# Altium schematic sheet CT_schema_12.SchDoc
size 386 x 278 mm
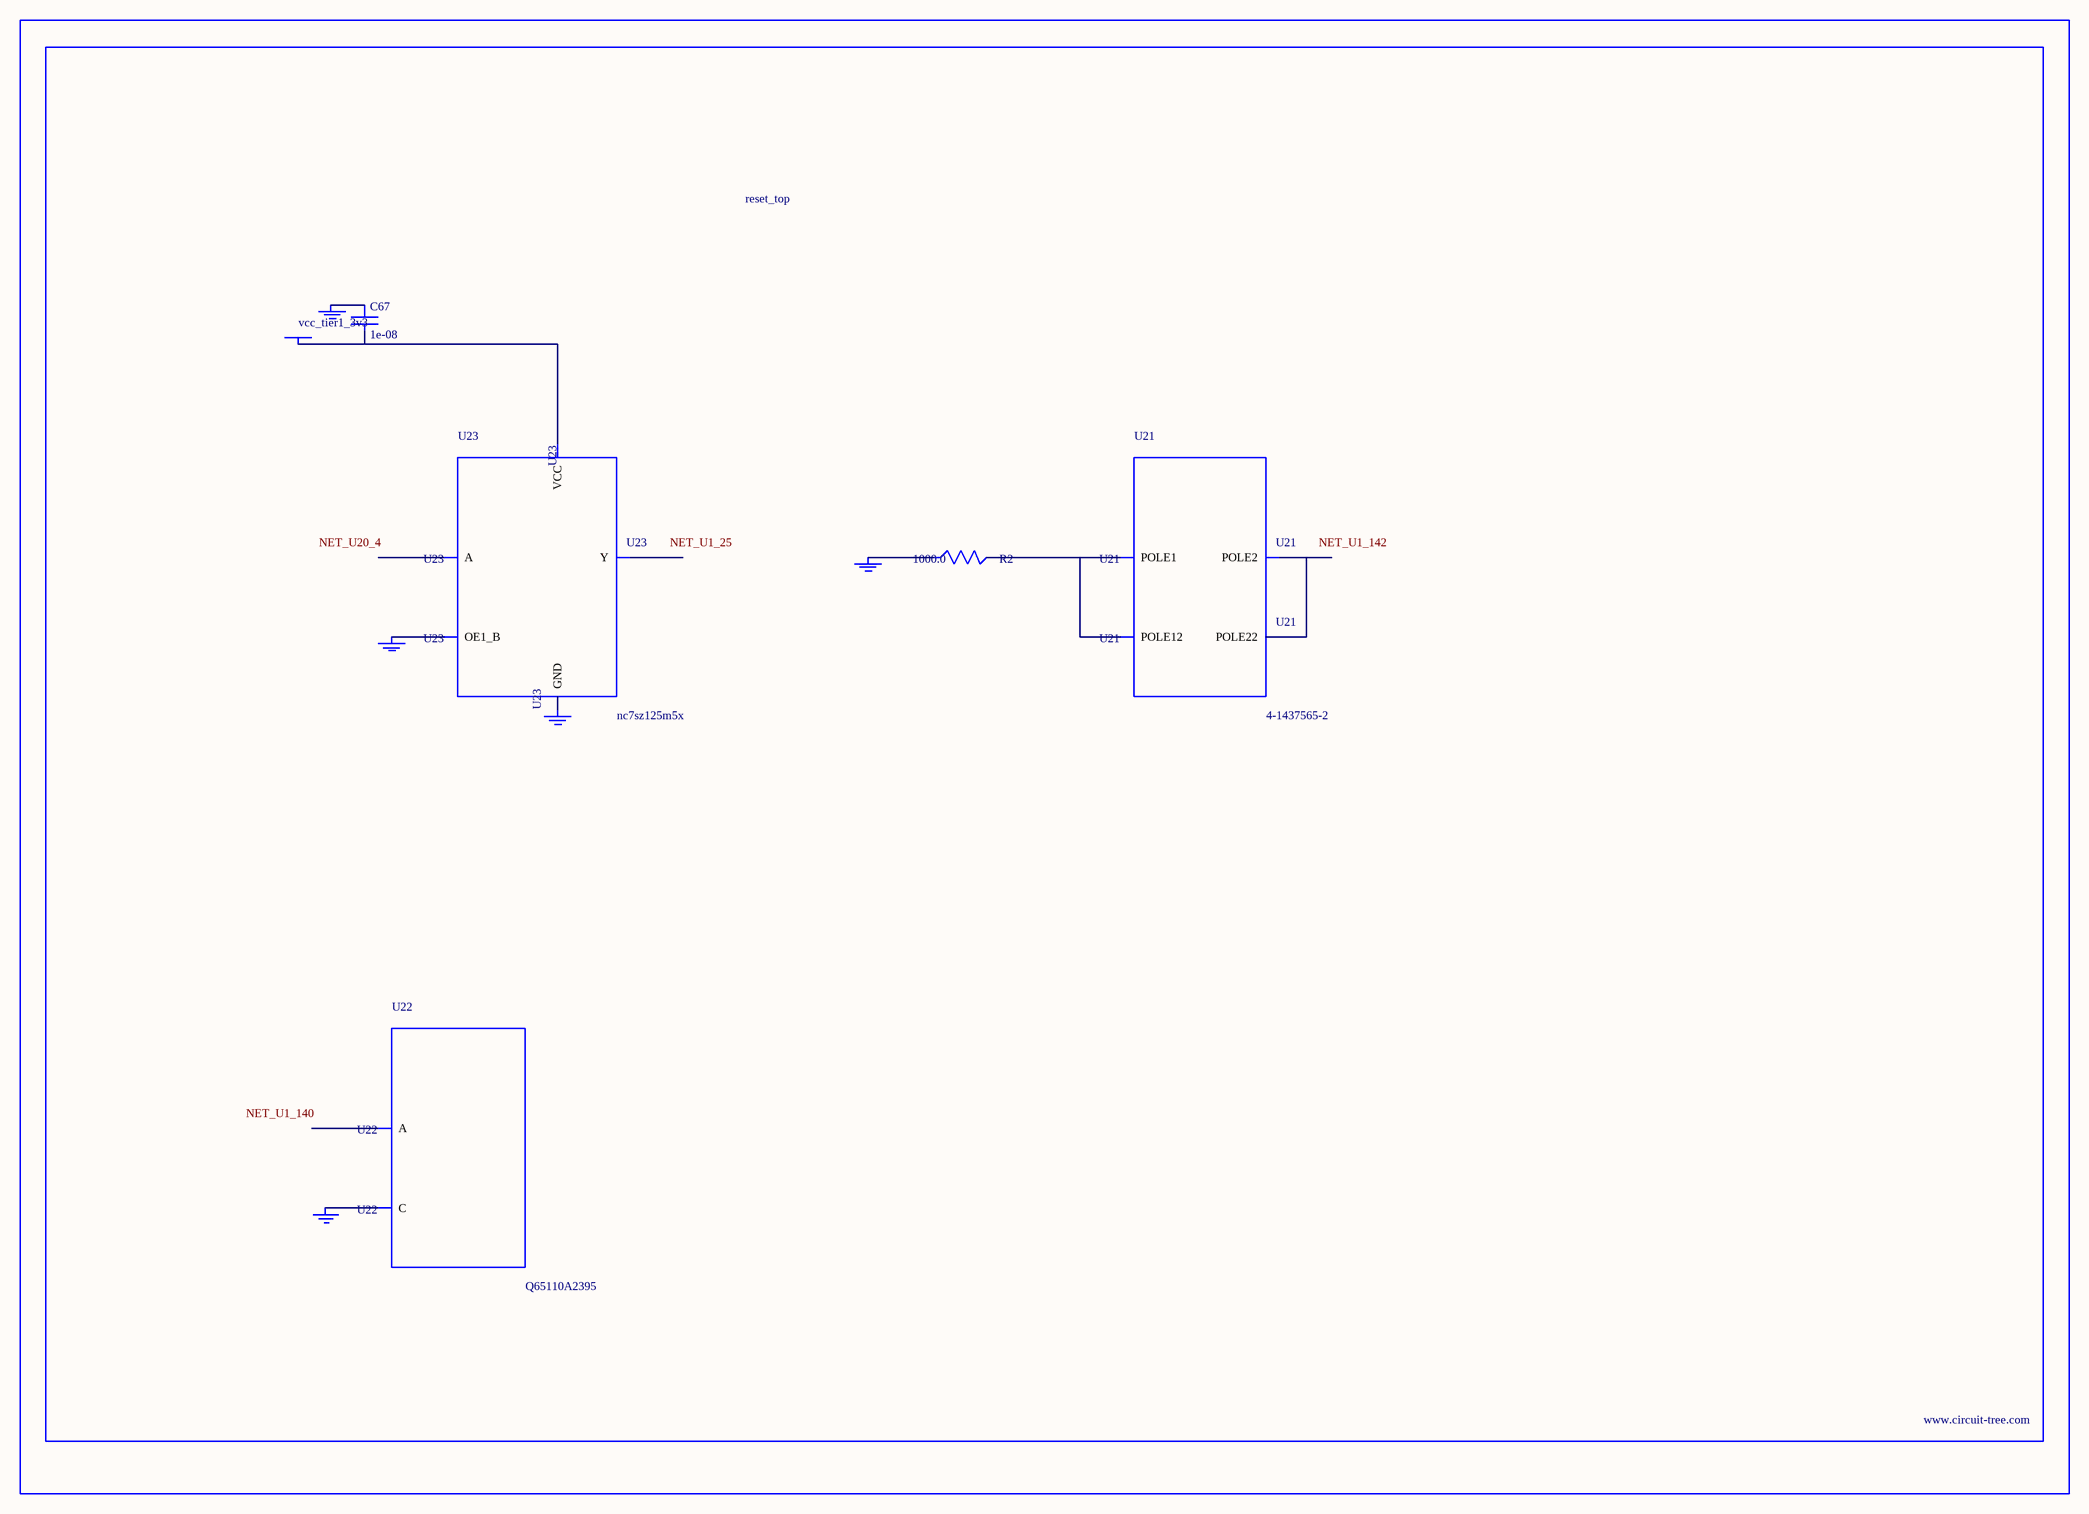
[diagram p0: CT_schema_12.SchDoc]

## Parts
BORDER11  (no value)
C67  1e-08  [C0402]
GND_INSTANCE_11_0  (no value)
GND_INSTANCE_11_1  (no value)
GND_INSTANCE_11_2  (no value)
GND_INSTANCE_11_3  (no value)
GND_INSTANCE_11_4  (no value)
POWER_INSTANCE_11_0  vcc_tier1_3v3
R2  1000.0  [R0603]
U21  4-1437565-2  [SW_4-1437565-2]
U22  Q65110A2395  [LGM67K-G1J2-24-Z]
U23  nc7sz125m5x  [NC7SZ125M5X]

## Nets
NetC67_1: C67.1 GND_INSTANCE_11_2.0(GND)
NetC67_2: C67.2 POWER_INSTANCE_11_0.0(PWR) U23.5(VCC)
NetGND_INSTANCE_11_0_0: GND_INSTANCE_11_0.0(GND) R2.1
NetGND_INSTANCE_11_1_0: GND_INSTANCE_11_1.0(GND) U22.C
NetGND_INSTANCE_11_3_0: GND_INSTANCE_11_3.0(GND) U23.1(OE1_B)
NetGND_INSTANCE_11_4_0: GND_INSTANCE_11_4.0(GND) U23.3(GND)
NetR2_2: R2.2 U21.1(POLE1) U21.2(POLE12)
NetU21_3: U21.3(POLE2) U21.4(POLE22)

Not connected (* = marked no-connect by the designer): U22 A; U23 2(A) 4(Y)

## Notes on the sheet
- Labels drawn without touching a wire or pin: NET_U1_25, NET_U1_140, NET_U1_142, NET_U20_4

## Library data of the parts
BORDER11 = BORDER_PAGE11
C67 = C0402C103K3RAC
GND_INSTANCE_11_0-GND_INSTANCE_11_4 = GND
POWER_INSTANCE_11_0 = PWR
R2 = RC0603JR-071KL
